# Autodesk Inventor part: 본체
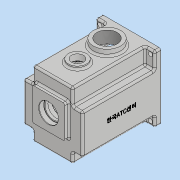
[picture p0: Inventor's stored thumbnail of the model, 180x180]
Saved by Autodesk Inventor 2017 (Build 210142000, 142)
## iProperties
Part Number: 본체
Material: 일반
Document SubType Name: Modeling
Designer: MRC
Density: 1 g/cm^3
Appearance: 기본값
Author: MRC
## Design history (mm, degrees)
sketch "스케치1"
  geometry: L1 (-49, 55)-(49, 55); L2 (49, 55)-(49, -55); L3 (49, -55)-(-49, -55); L4 (-49, -55)-(-49, 55); L5 (-49, 55)-(49, -55); L6 (49, 55)-(-49, -55); 1 further point
  constraints: 12 end point, 2 midpoint, 2 parallel, 1 horizontal, 1 perpendicular
  dimensions: "d0" = 98 distance of L2.end L3.end; "d1" = 110 distance of L1.end L2.end
extrude "돌출1" new body sketch "스케치1" stored distance "d2" = 130; taper "d3" = 0 deg
sketch "스케치4"
  geometry: L1 (0, 0)-(16, 0); L2 (16, 0)-(16, 120); L3 (16, 120)-(0, 120); L4 (0, 120)-(0, 0); L5 (0, 0)-(16, 120); L6 (16, 0)-(0, 120); L7 (98, 0)-(0, 0) reference; L8 (82, 0)-(98, 0); L9 (98, 0)-(98, 120); L10 (98, 120)-(82, 120); L11 (82, 120)-(82, 0); L12 (82, 0)-(98, 120); L13 (98, 0)-(82, 120); 3 further points
  constraints: 24 end point, 4 midpoint, 4 parallel, 2 collinear, 2 horizontal, 2 perpendicular
  dimensions: "d12" = 16 distance of L3.end L2.end; "d13" = 120 distance of L2.end L1.end; "d14" = 16 distance of L10.end L9.end; "d15" = 120 distance of L7.start L9.end
extrude "돌출4" cut sketch "스케치4" distance "d16" = 27; taper "d17" = 0 deg
sketch "스케치5"
  geometry: L1 (98, 0)-(82, 0); L2 (82, 0)-(82, -120); L3 (82, -120)-(98, -120); L4 (98, -120)-(98, 0); L5 (98, 0)-(82, -120); L6 (82, 0)-(98, -120); L7 (0, 0)-(98, 0) reference; L8 (16, 0)-(0, 0); L9 (0, 0)-(0, -120); L10 (0, -120)-(16, -120); L11 (16, -120)-(16, 0); L12 (16, 0)-(0, -120); L13 (0, 0)-(16, -120); 3 further points
  constraints: 24 end point, 4 midpoint, 4 parallel, 2 collinear, 2 horizontal, 2 perpendicular
  dimensions: "d18" = 16 distance of L3.end L2.end; "d19" = 120 distance of L2.end L1.end; "d20" = 16 distance of L10.end L9.end; "d21" = 120 distance of L7.start L9.end
extrude "돌출5" cut sketch "스케치5" distance "d22" = 17; taper "d23" = 0 deg
sketch "스케치9"
  geometry: L1 (49, 55)-(-49, 55) reference; L2 (-49, 55)-(-49, -55) reference; C1 r 3.5 at (-42, 48); 1 further point
  constraints: 1 centre point
  dimensions: "d31" = 7 diameter of C1; "d32" = 7 distance from line of C1.centre L1; "d33" = 7 distance from line of L2 C1.centre
extrude "돌출8" cut sketch "스케치9" stored distance "d34" = 8.3; taper "d35" = 0 deg
sketch "스케치2"
  geometry: L1 (0, 130)-(98, 130) reference; C1 r 22.5 at (49, 90); 1 further point
  constraints: 1 centre point, 1 vertical alignment
  dimensions: "d4" = 45 diameter of C1; "d5" = 40 distance from line of C1.centre L1
extrude "돌출2" join sketch "스케치2" distance "d6" = 10; taper "d7" = 0 deg
sketch "스케치3"
  geometry: C1 r 15 at (49, 41); C2 r 22.5 at (49, 90) reference; 1 further point
  constraints: 1 centre point, 1 vertical alignment
  dimensions: "d8" = 30 diameter of C1; "d9" = 49 distance of C1.centre C2.centre
extrude "돌출3" join sketch "스케치3" distance "d10" = 5; taper "d11" = 0 deg
sketch "스케치10"
  geometry: L1 (-49, -55)-(49, -55) reference; L2 (-23, 45)-(23, 45); L3 (-23, 45)-(-23, 30.143); L4 (23, 45)-(23, 30.143); A1 r 42 centre (0, -5) between (-23, 30.143) and (23, 30.143); 2 further points
  constraints: 6 end point, 2 point on circle, 2 vertical, 2 vertical alignment, 1 centre point, 1 horizontal, 1 midpoint
  dimensions: "d42" = 84 diameter of A1; "d43" = 50 distance from line of L1 A1.centre; "d45" = 50 distance from line of A1.centre L2; "d46" = 46 distance of L2.start L2.end
extrude "돌출9" cut sketch "스케치10" distance "d47" = 121; taper "d48" = 0 deg
fillet "모깎기1" dims "d49" = 6
fillet "모깎기2" dims "d50" = 3
sketch "스케치11"
  geometry: L1 (-20, 45)-(20, 45) reference; L2 (-23, 33.249)-(-23, 42) reference; L3 (23, 42)-(23, 33.249) reference; L4 (-26, 33.249)-(-26, 42); L5 (-20, 48)-(20, 48); L6 (26, 42)-(26, 33.249); A1 r 3 centre (20, 42) between (23, 42) and (20, 45) reference; A2 r 3 centre (-20, 42) between (-20, 45) and (-23, 42) reference; A3 r 6 centre (-29, 33.249) between (-25.375, 28.468) and (-23, 33.249) reference; A4 r 42 centre (0, -5) between (-25.375, 28.468) and (25.375, 28.468) reference; A5 r 6 centre (29, 33.249) between (23, 33.249) and (25.375, 28.468) reference; A6 r 45 centre (0, -5) between (-27.187, 30.859) and (27.188, 30.859); A7 r 3 centre (-29, 33.249) between (-27.187, 30.859) and (-26, 33.249); A8 r 6 centre (-20, 42) between (-20, 48) and (-26, 42); A9 r 6 centre (20, 42) between (26, 42) and (20, 48); A10 r 3 centre (29, 33.249) between (26, 33.249) and (27.188, 30.859); 1 further point
  constraints: 10 point on circle, 6 end point, 5 centre point, 7 other
  dimensions: "d51" = 3 radial gap between concentric circles of A4 A6
extrude "돌출10" cut sketch "스케치11" distance "d52" = 9; taper "d53" = 0 deg
hole "구멍1" diameter "d56" = 33.376; stored, may be unused: countersink angle "d60" = 90 deg, drill point angle "d62" = 118 deg; dims "d54" = 10, "d55" = 10, "d57" = 70, "d58" = 4, "d59" = 2, "d61" = 77.3
sketch "스케치12"
  geometry: C1 r 15 at (20, -32) reference; 1 further point
extrude "돌출11" cut sketch "스케치12" distance "d63" = 5; taper "d64" = 0 deg
sketch "스케치13"
  geometry: C1 r 10 at (0, 0); C2 r 15 at (0, 0) reference; 1 further point
  constraints: 1 centre point, 1 concentric
  dimensions: "d65" = 20 diameter of C1
extrude "돌출12" cut sketch "스케치13" stored distance "d66" = 5; taper "d67" = 0 deg
sketch "스케치14"
  geometry: A1 r 21 centre (0, 6) between (8.978, -12.984) and (-8.978, -12.984); A2 r 42 centre (0, -5) between (-25.375, 28.468) and (25.375, 28.468) reference; A3 r 15 centre (0, -25) between (-8.978, -12.984) and (8.978, -12.984); 1 further point
  constraints: 4 point on circle, 2 centre point, 2 vertical alignment
  dimensions: "d68" = 42 diameter of A1; "d69" = 11 distance of A1.centre A2.centre; "d70" = 30 diameter of A3; "d71" = 20 distance of A3.centre A2.centre
extrude "돌출13" join sketch "스케치14" distance "d72" = 7; taper "d73" = 0 deg
sketch "스케치15"
  geometry: C1 r 17.5 at (0, 6); A1 r 21 centre (0, 6) between (8.978, -12.984) and (-8.978, -12.984) reference; 1 further point
  constraints: 1 centre point, 1 concentric
  dimensions: "d74" = 35 diameter of C1
extrude "돌출14" cut sketch "스케치15" distance "d75" = 10; taper "d76" = 0 deg
sketch "스케치16"
  geometry: C1 r 14 at (0, 0); C2 r 17.5 at (0, 0) reference; 1 further point
  constraints: 1 centre point, 1 concentric
  dimensions: "d77" = 28 diameter of C1
extrude "돌출15" cut sketch "스케치16" stored distance "d78" = 10; taper "d79" = 0 deg
sketch "스케치17"
  geometry: L1 (-27, 33)-(27, 33); L2 (27, 33)-(27, -21); L3 (27, -21)-(-27, -21); L4 (-27, -21)-(-27, 33); L5 (-27, 33)-(27, -21); L6 (27, 33)-(-27, -21); C1 r 14 at (0, 6) reference; 1 further point
  constraints: 12 end point, 2 midpoint, 2 parallel, 1 horizontal, 1 perpendicular
  dimensions: "d80" = 54 distance of L2.end L3.end; "d81" = 54 distance of L1.end L2.end
extrude "돌출16" join sketch "스케치17" distance "d82" = 7; taper "d83" = 0 deg
sketch "스케치18"
  geometry: C1 r 14 at (0, 6) reference; C2 r 16 at (0, 6); 1 further point
  constraints: 1 centre point, 1 coincident
  dimensions: "d84" = 32 diameter of C2
extrude "돌출17" cut sketch "스케치18" distance "d85" = 8.3; taper "d86" = 0 deg
sketch "스케치19"
  geometry: C1 r 11 at (0, -25); A1 r 15 centre (0, -25) between (-8.978, -12.984) and (8.978, -12.984) reference; 1 further point
  constraints: 1 centre point, 1 concentric
  dimensions: "d87" = 22 diameter of C1
extrude "돌출18" cut sketch "스케치19" distance "d88" = 7; taper "d89" = 0 deg
sketch "스케치20"
  geometry: C1 r 9.5 at (0, 0); C2 r 11 at (0, 0) reference; 1 further point
  constraints: 1 centre point, 1 concentric
  dimensions: "d90" = 19 diameter of C1
extrude "돌출19" cut sketch "스케치20" distance "d91" = 3; taper "d92" = 0 deg
sketch "스케치21"
  geometry: L1 (-41.809, -9)-(-35.777, -9); L2 (-41.809, -1)-(-35.777, -1); L3 (35.777, -9)-(41.809, -9); L4 (35.777, -1)-(41.809, -1); A1 r 36 centre (0, -5) between (36, -5) and (-36, -5); A2 r 42 centre (0, -5) between (-25.375, 28.468) and (25.375, 28.468) reference; A3 r 4 centre (-36, -5) between (-36, -9) and (-36, -1); A4 r 4 centre (36, -5) between (36, -1) and (36, -9); 1 further point
  constraints: 14 point on circle, 8 end point, 4 horizontal, 4 point on line, 4 tangent, 3 centre point, 2 horizontal alignment, 1 concentric, 1 equal radius
  dimensions: "d93" = 72 diameter of A1; "d94" = 8 diameter of A3
extrude "돌출20" join sketch "스케치21" stored distance "d95" = 3; taper "d96" = 0 deg
fillet "모깎기3" dims "d97" = 3
fillet "모깎기4" dims "d98" = 3
fillet "모깎기5" dims "d99" = 3
fillet "모깎기6" dims "d100" = 3
sketch "스케치22"
  geometry: A1 r 4 centre (-36, -5) between (-36, -9) and (-36, -1) reference; 2 further points
  constraints: 1 coincident
hole "구멍2" sketch "스케치22" at (-36, -5) diameter "d101" = 3.242; stored, may be unused: countersink angle "d105" = 90 deg, drill point angle "d107" = 118 deg; dims "d102" = 7, "d103" = 4, "d104" = 2, "d106" = 9
fillet "모깎기7" dims "d108" = 3
fillet "모깎기8" dims "d109" = 3
fillet "모깎기9" dims "d110" = 3
fillet "모깎기10" dims "d111" = 3
chamfer "모따기1" distance "d112" = 1; stored, may be unused: second distance "d113" = 2, angle "d114" = 45 deg
chamfer "모따기2" distance "d115" = 0.8; stored, may be unused: second distance "d116" = 2, angle "d117" = 30 deg
sketch "스케치23"
  geometry: L1 (-130, 104)-(-130, 83) reference; L2 (-13, 80)-(-127, 80) reference; 2 further points
  constraints: 1 other
  dimensions: "d118" = 65 distance from line of L1 point (-65, 47); "d119" = 33 distance from line of point (-65, 47) L2
feature "엠보싱1" sketch "스케치23" dims "d120" = 0.5, "d121" = 0
fillet "모깎기11" dims "d122" = 0.3
fillet "모깎기12" dims "d123" = 3
node "솔리드1"
pattern_linear "직사각형 패턴1" dims "d38" = 96, "d41" = 84
mirror "미러1"
node "투영된 루프1"
